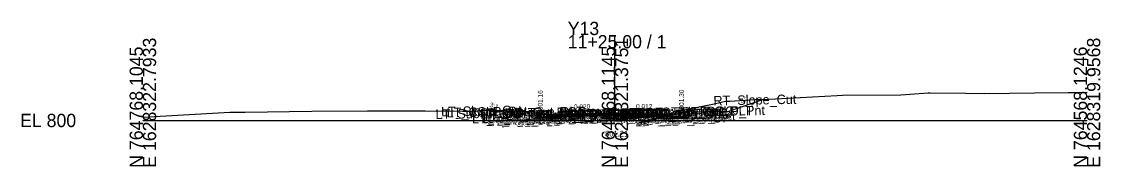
# Model space of a CAD drawing. Extents: x -26 to 203, y -10 to 3517.
# Drawn here: x -25.7 to 202.8, y 2490.3 to 2520.9 of the extents above; entities that cross this region are included whole.
import ezdxf

# ---------------------------------------------------------------- set-up
doc = ezdxf.new("R2010")
doc.units = 0
for name, color, linetype in [('Default', 7, 'Continuous'), ('Exist CMT Pavement', 7, 'Continuous'), ('Exist Cross Section Cell', 7, 'Continuous'), ('Exist XS Center Line Elevation Label', 7, 'Continuous'), ('Exist XS Ground Line', 7, 'Continuous'), ('Prop CMT Conc Surface', 7, 'Continuous'), ('Prop CMT Concrete Structures', 7, 'Continuous'), ('Prop CMT Pvmt Course 1', 7, 'Continuous'), ('Prop CMT Pvmt Course 1 CG', 7, 'Continuous'), ('Prop CMT Pvmt Course 1 Wedge', 7, 'Continuous'), ('Prop CMT Pvmt Course 2', 7, 'Continuous'), ('Prop CMT Pvmt Course 2 Wedge', 7, 'Continuous'), ('Prop CMT Pvmt Course 3', 7, 'Continuous'), ('Prop CMT Pvmt Surface', 7, 'Continuous'), ('Prop CMT Pvmt Wedge Surface 1', 7, 'Continuous'), ('Prop CMT Pvmt Wedge Surface 2', 7, 'Continuous'), ('Prop CMT Pvmt Wedge Surface 3', 7, 'Continuous'), ('Prop CMT Slope Grass', 7, 'Continuous'), ('Prop CMT Subgrade Earthwork', 7, 'Continuous'), ('Prop XS Hydro Elevations', 7, 'Continuous'), ('Prop XS SE Text', 7, 'Continuous'), ('Prop XS Side Slope Text', 7, 'Continuous'), ('Scratch_Level_0', 7, 'Continuous')]:
    doc.layers.add(name, color=color, linetype=linetype)

msp = doc.modelspace()

# ---------------------------------------------------------------- linework, layer by layer
at = {"layer": 'Exist CMT Pavement'}
for points in [[(100, 2501.21), (91.36, 2500.89), (88.17, 2500.78)], [(100, 2501.21), (100.02, 2501.21), (109.68, 2501.04), (111.72, 2500.97)]]:
    msp.add_lwpolyline(points, dxfattribs=at)
at = {"layer": 'Exist Cross Section Cell'}
for p, q in [((100, 2500), (100, 2518.03)), ((0, 2500), (100, 2500)), ((100, 2500), (200, 2500))]:
    msp.add_line(p, q, dxfattribs=at)
at = {"layer": 'Exist XS Ground Line'}
msp.add_lwpolyline([(0, 2500.71), (18.4, 2501.76), (21.67, 2501.77), (35.77, 2501.95), (47.55, 2502.01), (53.92, 2502.05), (59.8, 2502.03), (67.74, 2501.94), (69.85, 2501.94), (71.45, 2502.07), (74.66, 2502.18), (79.15, 2502.02), (82.92, 2501.87), (86.01, 2501.3), (88.1, 2500.77), (91.36, 2500.89), (100.02, 2501.21), (109.68, 2501.04), (112.01, 2500.96), (113.27, 2501.94), (115.7, 2502.43), (120.99, 2503.49), (123.44, 2504.09), (124.35, 2504.09), (129.73, 2504.41), (130.95, 2504.45), (131.41, 2504.46), (147.04, 2505.27), (148.2, 2505.32), (160.56, 2505.44), (166.38, 2505.86), (166.8, 2505.86), (174.25, 2505.77), (178.3, 2505.66), (188.91, 2505.84), (196, 2505.91), (197.52, 2505.93), (200, 2505.95)], dxfattribs=at)
at = {"layer": 'Prop CMT Conc Surface'}
for points in [[(84.17, 2501.16), (84.17, 2501.66), (83.67, 2501.66)], [(86.17, 2501.28), (84.17, 2501.16)], [(112.1, 2501.4), (114.1, 2501.3)], [(114.1, 2501.3), (114.1, 2501.8), (114.6, 2501.8)]]:
    msp.add_lwpolyline(points, dxfattribs=at)
at = {"layer": 'Prop CMT Concrete Structures'}
for points in [[(86.17, 2501.28), (84.17, 2501.16), (84.17, 2501.66), (83.67, 2501.66)], [(83.67, 2501.66), (83.67, 2500.64), (86.17, 2500.69)], [(86.17, 2500.69), (86.17, 2501.28)], [(112.1, 2501.4), (114.1, 2501.3), (114.1, 2501.8), (114.6, 2501.8)], [(114.6, 2501.8), (114.6, 2500.79), (112.1, 2500.82)], [(112.1, 2500.82), (112.1, 2501.4)]]:
    msp.add_lwpolyline(points, dxfattribs=at)
at = {"layer": 'Prop CMT Pvmt Course 1'}
for points in [[(100, 2501.55), (86.17, 2501.28)], [(86.17, 2501.28), (86.17, 2501.03)], [(86.17, 2501.03), (88.17, 2501.07)], [(88.17, 2501.19), (100, 2501.43)], [(88.17, 2501.07), (88.17, 2501.19)], [(100, 2501.3), (100, 2501.55)], [(100, 2501.55), (112.1, 2501.4)], [(100, 2501.3), (100, 2501.55)], [(100, 2501.43), (100, 2501.3), (100, 2501.3)], [(111.72, 2501.29), (100, 2501.43)], [(100, 2501.43), (100, 2501.3), (100, 2501.3)], [(111.72, 2501.16), (111.72, 2501.29)], [(112.1, 2501.15), (111.72, 2501.16)], [(112.1, 2501.4), (112.1, 2501.15)]]:
    msp.add_lwpolyline(points, dxfattribs=at)
at = {"layer": 'Prop CMT Pvmt Course 1 CG'}
for points in [[(86.17, 2500.69), (83.17, 2500.63), (82.83, 2500.29)], [(82.83, 2500.29), (86.17, 2500.36)], [(86.17, 2500.36), (86.17, 2500.69)], [(112.1, 2500.82), (115.1, 2500.78), (115.44, 2500.45)], [(112.1, 2500.49), (112.1, 2500.82)], [(115.44, 2500.45), (112.1, 2500.49)]]:
    msp.add_lwpolyline(points, dxfattribs=at)
at = {"layer": 'Prop CMT Pvmt Course 1 Wedge'}
for points in [[(88.17, 2501.19), (91.36, 2501.25), (100, 2501.43)], [(100, 2501.3), (91.36, 2501.13), (88.17, 2501.07)], [(88.17, 2501.07), (88.17, 2501.19)], [(100, 2501.43), (100, 2501.3)], [(100, 2501.43), (100.02, 2501.43), (109.68, 2501.31), (111.72, 2501.29)], [(100, 2501.3), (100, 2501.43)], [(111.72, 2501.16), (109.68, 2501.18), (100.02, 2501.3), (100, 2501.3)], [(111.72, 2501.29), (111.72, 2501.16)]]:
    msp.add_lwpolyline(points, dxfattribs=at)
at = {"layer": 'Prop CMT Pvmt Course 2'}
for points in [[(88.17, 2501.07), (86.17, 2501.03)], [(86.17, 2501.03), (86.17, 2500.69)], [(86.17, 2500.69), (88.17, 2500.73)], [(88.17, 2500.73), (88.17, 2501.07)], [(111.72, 2500.83), (111.72, 2501.16)], [(111.72, 2501.16), (112.1, 2501.15)], [(112.1, 2500.82), (111.72, 2500.83)], [(112.1, 2501.15), (112.1, 2500.82)]]:
    msp.add_lwpolyline(points, dxfattribs=at)
at = {"layer": 'Prop CMT Pvmt Course 2 Wedge'}
for points in [[(88.17, 2501.07), (91.36, 2501.13), (100, 2501.3)], [(100, 2501.21), (91.36, 2500.89), (88.17, 2500.77)], [(88.17, 2500.77), (88.17, 2501.07)], [(100, 2501.3), (100, 2501.21)], [(100, 2501.3), (100.02, 2501.3), (109.68, 2501.18), (111.72, 2501.16)], [(100, 2501.21), (100, 2501.3)], [(111.72, 2500.97), (109.68, 2501.04), (100.02, 2501.21), (100, 2501.21)], [(111.72, 2501.16), (111.72, 2500.97)]]:
    msp.add_lwpolyline(points, dxfattribs=at)
at = {"layer": 'Prop CMT Pvmt Course 3'}
for points in [[(88.17, 2500.73), (86.17, 2500.69)], [(86.17, 2500.69), (86.17, 2500.36)], [(86.17, 2500.36), (88.17, 2500.4)], [(88.17, 2500.4), (88.17, 2500.73)], [(111.72, 2500.83), (112.1, 2500.82)], [(111.72, 2500.49), (111.72, 2500.83)], [(112.1, 2500.49), (111.72, 2500.49)], [(112.1, 2500.82), (112.1, 2500.49)]]:
    msp.add_lwpolyline(points, dxfattribs=at)
at = {"layer": 'Prop CMT Pvmt Surface'}
for points in [[(100, 2501.55), (86.17, 2501.28)], [(100, 2501.55), (112.1, 2501.4)]]:
    msp.add_lwpolyline(points, dxfattribs=at)
at = {"layer": 'Prop CMT Pvmt Wedge Surface 1'}
for points in [[(86.17, 2501.03), (86.17, 2501.28)], [(88.17, 2501.07), (86.17, 2501.03)], [(100, 2501.43), (88.17, 2501.19)], [(88.17, 2501.19), (88.17, 2501.07)], [(100, 2501.43), (111.72, 2501.29)], [(111.72, 2501.29), (111.72, 2501.16)], [(111.72, 2501.16), (112.1, 2501.15)], [(112.1, 2501.15), (112.1, 2501.4)]]:
    msp.add_lwpolyline(points, dxfattribs=at)
at = {"layer": 'Prop CMT Pvmt Wedge Surface 2'}
for points in [[(100, 2501.3), (86.17, 2501.03)], [(86.17, 2501.03), (86.17, 2501.28)], [(100, 2501.3), (112.1, 2501.15)], [(112.1, 2501.15), (112.1, 2501.4)]]:
    msp.add_lwpolyline(points, dxfattribs=at)
at = {"layer": 'Prop CMT Pvmt Wedge Surface 3'}
for points in [[(86.17, 2500.69), (86.17, 2501.28)], [(100, 2500.97), (86.17, 2500.69)], [(100, 2500.97), (112.1, 2500.82)], [(112.1, 2500.82), (112.1, 2501.4)]]:
    msp.add_lwpolyline(points, dxfattribs=at)
at = {"layer": 'Prop CMT Slope Grass'}
for points in [[(114.6, 2501.8), (124.1, 2501.99), (131.53, 2504.47)], [(83.67, 2501.66), (74.17, 2501.85), (73.31, 2502.13)]]:
    msp.add_lwpolyline(points, dxfattribs=at)
at = {"layer": 'Prop CMT Subgrade Earthwork'}
for points in [[(86.17, 2500.36), (82.83, 2500.29), (81.42, 2501.7)], [(88.17, 2500.4), (86.17, 2500.36)], [(88.17, 2500.4), (88.18, 2500.78)], [(111.72, 2500.49), (111.71, 2500.97)], [(111.72, 2500.49), (112.1, 2500.49)], [(112.1, 2500.49), (115.44, 2500.45), (116.84, 2501.84)]]:
    msp.add_lwpolyline(points, dxfattribs=at)

# ---------------------------------------------------------------- texts
at = {"layer": 'Default'}
msp.add_text('-', height=0.0001, dxfattribs=at).set_placement((0, 2500))
at = {"layer": 'Exist Cross Section Cell'}
for s, p in [('Y13', (90, 2518.03)), ('11+25.00 / 1', (90, 2515.23)), ('EL 800', (-26, 2498.6))]:
    msp.add_text(s, height=2.8, dxfattribs=at).set_placement(p)
for s, p in [('E 1628322.7933', (2.8, 2490)), ('E 1628321.3751', (102.8, 2490)), ('E 1628319.9568', (202.8, 2490)), ('N 764768.1045', (0, 2490)), ('N 764668.1145', (100, 2490)), ('N 764568.1246', (200, 2490))]:
    msp.add_text(s, height=2.8, rotation=90, dxfattribs=at).set_placement(p)
at = {"layer": 'Exist XS Center Line Elevation Label'}
msp.add_text('801.21', height=1.2, dxfattribs=at).set_placement((97.9, 2496.61))
at = {"layer": 'Prop XS Hydro Elevations'}
for s, p in [('801.16', (84.67, 2502.16)), ('801.30', (114.6, 2502.3))]:
    msp.add_text(s, height=1, rotation=90, dxfattribs=at).set_placement(p)
at = {"layer": 'Prop XS SE Text'}
for s, rotation, p in [('0.020', 1.1458, (91.32, 2502.38)), ('0.012', 359.3008, (104.47, 2502.5))]:
    msp.add_text(s, height=1, rotation=rotation, dxfattribs=at).set_placement(p)
at = {"layer": 'Prop XS Side Slope Text'}
for rotation, p in [(18.4332, (126.7, 2503.65)), (341.5668, (73.34, 2502.91))]:
    msp.add_text('3:1', height=1, rotation=rotation, dxfattribs=at).set_placement(p)
at = {"layer": 'Scratch_Level_0'}
for s, p in [('RT_Slope_Cut', (120.89, 2503.17)), ('LT_Sub_Trench_Out_DLT', (62.01, 2500.31)), ('LT_Slope_Cut', (63.19, 2500.85)), ('LT_CSLP_Pnt', (64.37, 2500.65)), ('LT_CG_Top_Face', (71.45, 2500.4)), ('LT_CG_Top_BOC', (71.98, 2500.42)), ('LT_PV1_OEOT', (76.93, 2500.09)), ('RT_PV_IEEOP_EG', (88.16, 2499.97)), ('LT_PV_IEEOP_EG', (88.21, 2499.97)), ('RT_PV2_IEEOP', (89.93, 2500.1)), ('LT_PV2_IEEOP', (89.97, 2500.1)), ('RT_PV1_IEEOP', (90.49, 2500.24)), ('LT_PV1_IEEOP', (90.54, 2500.24)), ('PV1_PGL', (94.49, 2500.44)), ('RT_Sub_Trench_Out_DLT', (97.38, 2500.46)), ('RT_CG_Top_Face', (101.34, 2500.54)), ('RT_PV1_OEEOP', (101.57, 2500.08)), ('RT_CG_Top_Gut', (102.31, 2500.06)), ('RT_PV1_OEOT', (102.82, 2500.22)), ('RT_CG_Top_BOC', (102.86, 2500.56)), ('RT_CSLP_Pnt', (114.25, 2500.79)), ('LT_CG1_Shelf_Out', (69.75, 2499.36)), ('LT_CG_Bot_BOC', (72.01, 2499.41)), ('LT_CG_Top_Gut', (72.43, 2499.92)), ('LT_Sub_OEOP', (72.96, 2499.09)), ('LT_PV_Sub_Tie_Out', (73.15, 2499.48)), ('LT_PV_OEEOP_EG', (75.73, 2499.53)), ('LT_CG_Bot_IE', (76.11, 2499.49)), ('LT_Sub_OEOT', (76.27, 2499.16)), ('LT_PV2_OEOT', (76.37, 2499.83)), ('LT_PV3_OEOT', (76.37, 2499.5)), ('LT_Sub_OEEOP', (77.4, 2499.18)), ('LT_PV2_OEEOP', (77.5, 2499.85)), ('LT_PV3_OEEOP', (77.5, 2499.52)), ('LT_PV1_OEEOP', (78.06, 2499.99)), ('RT_PV3_IEEOP', (89.93, 2499.77)), ('LT_PV3_IEEOP', (89.97, 2499.77)), ('PV2_PGL', (93.93, 2500.18)), ('RT_PV_Sub_Tie_Out', (96.63, 2499.66)), ('RT_PV_OEEOP_EG', (99.24, 2499.72)), ('RT_Sub_OEEOP', (100.91, 2499.28)), ('RT_PV2_OEEOP', (101, 2499.95)), ('RT_PV3_OEEOP', (101, 2499.61)), ('RT_CG1_Shelf_Out', (101.63, 2499.51)), ('RT_CG_Bot_IE', (101.99, 2499.62)), ('RT_Sub_OEOT', (102.15, 2499.29)), ('RT_PV2_OEOT', (102.25, 2499.96)), ('RT_PV3_OEOT', (102.25, 2499.62)), ('RT_CG_Bot_BOC', (102.89, 2499.56)), ('RT_Sub_OEOP', (105.52, 2499.25))]:
    msp.add_text(s, height=2, rotation=1.1458, dxfattribs=at).set_placement(p)

doc.saveas('drawing.dxf')
